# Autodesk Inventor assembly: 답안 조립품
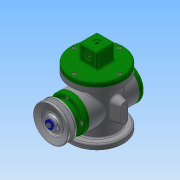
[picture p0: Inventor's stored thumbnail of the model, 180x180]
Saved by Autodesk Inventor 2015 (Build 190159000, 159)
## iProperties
Created: 2018-02
Part Number: 답안 조립품
Document SubType Name: Assembly
Designer: user
Author: user
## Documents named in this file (18)
- C:\Users\user\Desktop\480207V1011\답안 조립품.iam
- C:\Users\user\Desktop\480207V1011\1.본체.ipt
- C:\Users\user\Desktop\480207V1011\덮개.ipt
- C:\Users\user\Desktop\480207V1011\편심축.ipt
- C:\Users\user\Desktop\480207V1011\베어링 17 x 40 x 12.ipt
- C:\Users\user\Desktop\480207V1011\링크.ipt
- C:\Users\user\Desktop\480207V1011\슬라이더.ipt
- C:\Users\user\Desktop\480207V1011\클레비스 핀 6 x 22.ipt
- 클레비스 핀 6 x 22.ipt
- C:\Users\user\Desktop\480207V1011\뒤커버.ipt
- C:\Users\user\Desktop\480207V1011\볼트 M4 x 8.ipt
- C:\Users\user\Desktop\480207V1011\키 4 x 4 x 12.ipt
- C:\Users\user\Desktop\480207V1011\앞커버.ipt
- C:\Users\user\Desktop\480207V1011\오일 실 17 30 8.ipt
- C:\Users\user\Desktop\480207V1011\V-벨트풀리.ipt
- C:\Users\user\Desktop\480207V1011\볼트 M4 x 10.ipt
- C:\Users\user\Desktop\480207V1011\와셔 4x16.ipt
- C:\Users\user\Desktop\480207V1011\E-링.ipt
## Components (3 placed, 3 different names)
1. 1.본체:1 — 각도:1, 각도:3, 각도:5, 각도:6
2. V-벨트풀리:1 — 각도:4
3. E-링:1
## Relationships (5: Angle 5)
- 각도:1 [Angle]: 1.본체:1
- 각도:3 [Angle]: 1.본체:1
- 각도:4 [Angle]: V-벨트풀리:1
- 각도:5 [Angle]: 1.본체:1
- 각도:6 [Angle]: 1.본체:1
